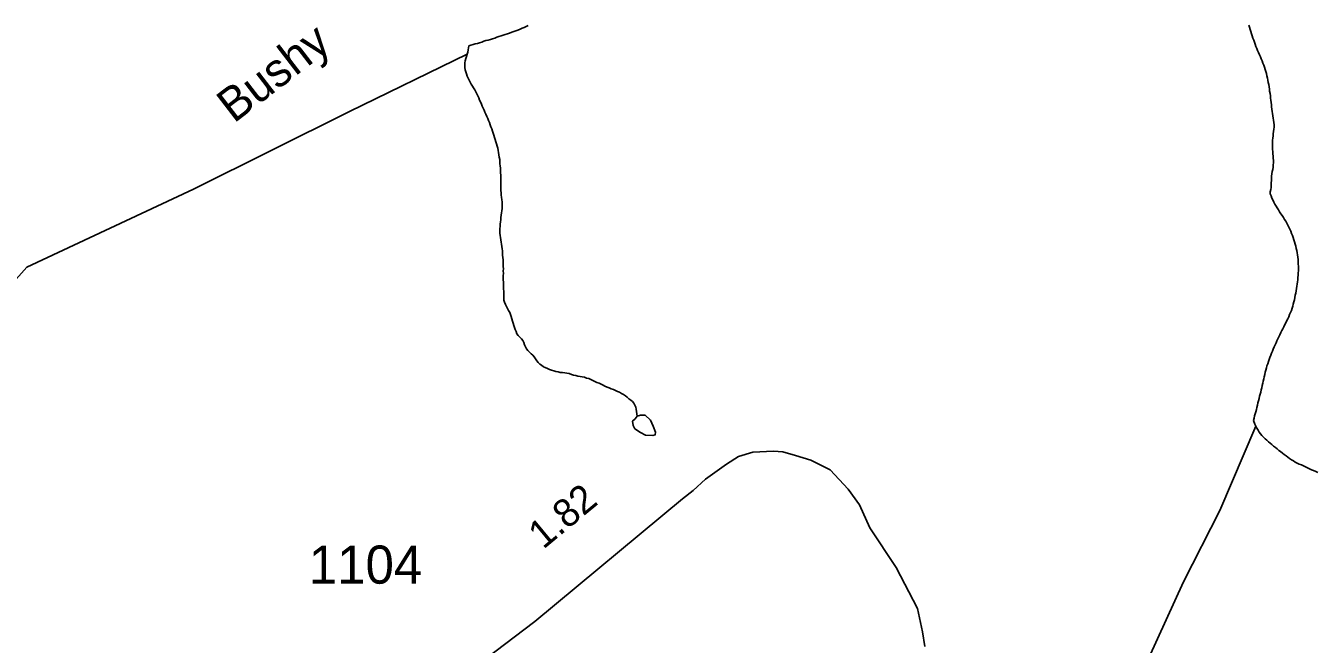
# Model space of a CAD drawing. Extents: x 1950930 to 2061844, y 904556 to 1017002.
# Drawn here: x 1968619 to 1974370, y 911322 to 914077 of the extents above; entities that cross this region are included whole.
import ezdxf

# ---------------------------------------------------------------- set-up
doc = ezdxf.new("R2010")
doc.units = 0
for name, color, linetype in [('Exist Hydrographic Creek Single Shore', 7, 'Continuous'), ('Exist Hydrographic Creek Single Shore Label', 7, 'Continuous'), ('Exist Hydrographic Misc Water Feature', 7, 'Continuous'), ('Exist Road Primary US Structure Standard Bridge CELL', 7, 'Continuous'), ('Exist Road Secondary Type 51 Attributed', 7, 'Continuous'), ('Exist Road Secondary Type 51 Number Label', 7, 'Continuous')]:
    doc.layers.add(name, color=color, linetype=linetype)

msp = doc.modelspace()

# ---------------------------------------------------------------- linework, layer by layer
at = {"layer": 'Exist Hydrographic Creek Single Shore'}
for points in [[(1970593.6, 913987.5), (1970603.4, 913990), (1970613.3, 913993), (1970622.3, 913996.1), (1970631.9, 913998.2), (1970641.4, 914001.3), (1970651.2, 914004.3), (1970660.6, 914007.7), (1970670.1, 914010.6), (1970679.9, 914012.9), (1970689.8, 914015.9), (1970699.2, 914018.8), (1970709, 914021.8), (1970718.5, 914025.3), (1970727.9, 914028.3), (1970737.3, 914031.3), (1970746.8, 914034.3), (1970756.2, 914037.4), (1970765.6, 914040.8), (1970775.1, 914043.9), (1970784.7, 914047.7), (1970794.1, 914050.7), (1970803.1, 914054.5), (1970812.2, 914057.7), (1970821.8, 914061.5), (1970831, 914065.4), (1970840.1, 914069.7), (1970849.7, 914073.1), (1970858.5, 914077.4)], [(1974201.5, 913256), (1974196.1, 913265), (1974191.2, 913273.5), (1974186.3, 913282.7), (1974181.6, 913291.6), (1974177.1, 913300.7), (1974172.6, 913309.2), (1974169.1, 913319), (1974165.4, 913328.1), (1974164.8, 913337.1), (1974168.3, 913346.8), (1974169.1, 913356.8), (1974169.3, 913366.5), (1974169.9, 913377.3), (1974170.3, 913387.1), (1974170.7, 913397.1), (1974171.3, 913406.8), (1974172.2, 913416.8), (1974174.4, 913427), (1974176, 913436.9), (1974177.7, 913446.7), (1974178.9, 913456.8), (1974179.1, 913466.4), (1974179.1, 913476.2), (1974178.7, 913486.4), (1974178.3, 913496.3), (1974177.3, 913505.7), (1974176.5, 913516.4), (1974175.6, 913526.2), (1974174.8, 913536.6), (1974174.6, 913546.3), (1974174.6, 913556), (1974175.4, 913566.8), (1974176.3, 913576.4), (1974177.5, 913586.4), (1974178.7, 913596), (1974179.9, 913606), (1974181.6, 913615.8), (1974182, 913625.6), (1974182, 913636), (1974181.2, 913646.4), (1974179.7, 913655.9), (1974178.1, 913665.8), (1974176.3, 913675.9), (1974175.4, 913685.7), (1974173.6, 913695.4), (1974172.8, 913705.2), (1974171.3, 913715.2), (1974170.5, 913725.1), (1974169.1, 913735), (1974167.8, 913745), (1974166.8, 913754.8), (1974165.6, 913764.8), (1974164.4, 913775.1), (1974162.5, 913785.1), (1974161.3, 913795), (1974160.1, 913805), (1974158.2, 913814.6), (1974156.4, 913823.8), (1974154.5, 913833.8), (1974152.5, 913843.5), (1974150.6, 913853.5), (1974148.6, 913863.5), (1974145.5, 913873.4), (1974142.6, 913882.3), (1974139.8, 913892.4), (1974136.1, 913901.6), (1974132.6, 913910.6), (1974129.1, 913920.5), (1974125, 913929.6), (1974121.1, 913938.8), (1974117, 913947.9), (1974113.1, 913957), (1974109, 913966.1), (1974105.1, 913975.3), (1974101.6, 913984.7), (1974098.3, 913994.1), (1974094.8, 914003.2), (1974091.4, 914013.1), (1974088.3, 914022), (1974085.2, 914031.9), (1974081.7, 914041.3), (1974078.6, 914051.1), (1974075.6, 914060.9), (1974072.9, 914070.2), (1974070.2, 914079.9)], [(1970586.4, 913949.9), (1970588.9, 913959.7), (1970590.7, 913969.6), (1970593.6, 913987.5)], [(1968138.7, 912457.9), (1968623.6, 913001.1), (1969367.4, 913348.2), (1970061.6, 913695.3), (1970586.4, 913949.9)], [(1970747.6, 912994.1), (1970747.2, 913003.9), (1970747, 913013.7), (1970746.6, 913023.4), (1970746.6, 913033.6), (1970745.7, 913044.2), (1970744.5, 913054.2), (1970743.5, 913063.7), (1970743.1, 913073.9), (1970741.6, 913083.5), (1970740.8, 913093.3), (1970739.4, 913103.3), (1970738.1, 913113.2), (1970736.3, 913123.2), (1970734.2, 913132.9), (1970732.8, 913142.9), (1970732, 913152.7), (1970731.4, 913162.5), (1970732, 913173), (1970732.8, 913183), (1970733.6, 913193), (1970734.7, 913202.6), (1970735.9, 913212.6), (1970736.7, 913222.2), (1970738.6, 913232.9), (1970739.8, 913242.8), (1970741.4, 913252.8), (1970742.7, 913262.7), (1970742.7, 913272.5), (1970742, 913282.2), (1970741.6, 913292), (1970740.6, 913302), (1970740, 913312.6), (1970738.6, 913322.6), (1970738.1, 913332.3), (1970736.7, 913342.3), (1970736.3, 913352.1), (1970735.9, 913362), (1970735.7, 913371.7), (1970735.7, 913382.3), (1970735.7, 913392.4), (1970736.1, 913402), (1970736.1, 913411.8), (1970735.5, 913421.6), (1970734.9, 913432.3), (1970734.5, 913442.5), (1970733.8, 913452.3), (1970732.4, 913461.8), (1970731.6, 913471.8), (1970731.2, 913481.5), (1970729.3, 913491.5), (1970728.1, 913501.5), (1970726.3, 913511.5), (1970724.4, 913521.1), (1970722.4, 913531.1), (1970719.7, 913540.9), (1970717.2, 913551), (1970714.4, 913559.9), (1970711.3, 913569.8), (1970708.2, 913579.2), (1970705.5, 913588.9), (1970702.5, 913597.9), (1970699, 913607.8), (1970696.3, 913617.1), (1970692.4, 913627), (1970689.3, 913636), (1970685.2, 913645.1), (1970681.8, 913655.1), (1970678.3, 913664.1), (1970673.8, 913673.3), (1970669.9, 913682.5), (1970665.8, 913691.6), (1970661.9, 913700.7), (1970657.8, 913709.8), (1970653.9, 913719), (1970649.8, 913728.1), (1970645.9, 913737.2), (1970641.8, 913745.9), (1970637.7, 913755), (1970633.8, 913764.2), (1970628.9, 913773.5), (1970624.5, 913782.6), (1970620, 913791.8), (1970615.1, 913799.9), (1970610, 913808.4), (1970604.7, 913817.3), (1970599.3, 913825.9), (1970595, 913835), (1970590.3, 913843), (1970586.4, 913853), (1970582.9, 913862.4), (1970579.8, 913872.2), (1970577.6, 913881.1), (1970575.3, 913891.2), (1970575.3, 913900.9), (1970575.9, 913911.8), (1970577.8, 913921.2), (1970580.3, 913931), (1970583.5, 913940.2), (1970586.4, 913949.9)], [(1974090.3, 912318.9), (1974092.8, 912328.6), (1974095.3, 912338.4), (1974098.1, 912348.1), (1974100.6, 912357.1), (1974103.5, 912366.8), (1974105.5, 912376.7), (1974108, 912386.8), (1974110.4, 912396.6), (1974113.5, 912406.3), (1974116, 912416.1), (1974118, 912425.9), (1974120.7, 912434.8), (1974122.7, 912444.7), (1974125.2, 912454.4), (1974127.2, 912464.2), (1974129.7, 912474), (1974131.8, 912483.8), (1974134, 912493.7), (1974136.5, 912503.4), (1974138.5, 912513.2), (1974140.6, 912523.1), (1974143, 912532.8), (1974145.9, 912542.6), (1974148, 912552.4), (1974150.6, 912561.3), (1974153.7, 912571), (1974157, 912580.7), (1974160.3, 912589.9), (1974163.9, 912599.5), (1974167.6, 912608.7), (1974171.3, 912618.2), (1974174.8, 912627.5), (1974178.9, 912636.2), (1974182.6, 912646.1), (1974186.7, 912654.8), (1974191.2, 912664), (1974195.1, 912672.7), (1974199.4, 912682.5), (1974203.3, 912691.2), (1974207.8, 912700.4), (1974211.9, 912709.5), (1974217.3, 912718.4), (1974221.8, 912727), (1974226.1, 912736.1), (1974230.6, 912745.2), (1974235.1, 912753.9), (1974239.2, 912763), (1974243.5, 912771.6), (1974247.6, 912780.7), (1974251.7, 912789.9), (1974255.8, 912799.4), (1974259.5, 912808.5), (1974262.4, 912818.3), (1974265.2, 912828), (1974267.7, 912836.9), (1974270.6, 912846.7), (1974272.6, 912856.5), (1974274.7, 912866.3), (1974276.7, 912876.2), (1974278.8, 912885.9), (1974280.8, 912895.8), (1974282.3, 912906.5), (1974283.9, 912916.5), (1974284.9, 912926), (1974286.6, 912935.9), (1974287.4, 912945.5), (1974288.6, 912955.4), (1974289.4, 912965.5), (1974290.3, 912975.1), (1974290.7, 912986), (1974290.7, 912995.7), (1974290.7, 913005.5), (1974290.1, 913015.3), (1974289.9, 913026), (1974289.2, 913035.7), (1974288, 913045.7), (1974287, 913055.6), (1974285.7, 913065.6), (1974283.7, 913075.6), (1974281.4, 913085.2), (1974279.2, 913094.6), (1974276.5, 913104.2), (1974273, 913114.2), (1974270.4, 913123.5), (1974266.9, 913133.3), (1974263.6, 913142.3), (1974260.1, 913151.4), (1974256.2, 913161.3), (1974252.3, 913170.4), (1974247.8, 913179.7), (1974243.7, 913188), (1974238.8, 913196.8), (1974233.9, 913206.1), (1974229, 913214.1), (1974224, 913222.6), (1974218.1, 913231.2), (1974212.8, 913239.3), (1974206.8, 913247.5), (1974201.5, 913256)], [(1971343.3, 912337.7), (1971341.8, 912347.7), (1971341, 912357.6), (1971340.2, 912368.3), (1971337.9, 912377.9), (1971334.2, 912386.2), (1971328.5, 912394.8), (1971322.5, 912402.2), (1971315.2, 912409), (1971307.4, 912415.4), (1971299.2, 912422.4), (1971291.2, 912428), (1971283.2, 912434.1), (1971274.6, 912439.1), (1971265.3, 912444.6), (1971256.1, 912448), (1971246.9, 912451.4), (1971237.9, 912455.6), (1971228.4, 912459.9), (1971219.2, 912463.3), (1971210, 912466.8), (1971200.5, 912471.1), (1971191.9, 912475.2), (1971182.9, 912479.8), (1971173.9, 912484), (1971164.7, 912488.2), (1971155.6, 912492.5), (1971146.6, 912496.7), (1971137.4, 912500.1), (1971127.9, 912504.8), (1971118.7, 912507.5), (1971108.9, 912510.6), (1971099, 912512.4), (1971089.2, 912514.4), (1971079.8, 912516.2), (1971069.9, 912518.2), (1971060.1, 912520.8), (1971050.8, 912523.5), (1971041.2, 912527), (1971031.2, 912528.8), (1971021.3, 912530.4), (1971011.3, 912531.5), (1971001.2, 912532.6), (1970991.4, 912534.6), (1970982, 912536.4), (1970972.1, 912539.1), (1970962.5, 912541.7), (1970953.2, 912545.2), (1970944.2, 912549.4), (1970934.6, 912553.7), (1970926, 912557.8), (1970917.8, 912564), (1970909.8, 912569.6), (1970902.8, 912576.4), (1970896.9, 912584.6), (1970891.1, 912593.2), (1970884.8, 912601.4), (1970878.4, 912608.9), (1970871, 912615.8), (1970864.3, 912623.3), (1970856.9, 912630), (1970851.1, 912638.2), (1970846, 912646.7), (1970842.5, 912655.8), (1970838.6, 912665.7), (1970834.1, 912674.1), (1970827.8, 912682.4), (1970820.8, 912689.1), (1970813.6, 912696.7), (1970808.1, 912704.9), (1970804.2, 912714), (1970800.5, 912723), (1970797.4, 912732), (1970794.3, 912741.9), (1970791.5, 912752), (1970788.6, 912760.9), (1970785.9, 912770.7), (1970783, 912780.9), (1970778.9, 912790.1), (1970775.9, 912799.1), (1970771, 912808.3), (1970766.4, 912817.1), (1970761.3, 912826.5), (1970757.2, 912834.8), (1970753.3, 912844.7), (1970750.4, 912853.6), (1970749.6, 912863.5), (1970750, 912873.6), (1970750, 912884.1), (1970749.6, 912893.9), (1970749, 912903.8), (1970748.2, 912913.6), (1970748.2, 912923.4), (1970747.8, 912934), (1970747.4, 912944.2), (1970747.2, 912953.9), (1970747.2, 912963.7), (1970747.6, 912973.4), (1970747.2, 912984.4), (1970747.6, 912994.1)], [(1974377.2, 912086.5), (1974368, 912090.7), (1974358.5, 912095), (1974349.3, 912098.5), (1974340.3, 912102.7), (1974331.3, 912107.3), (1974322.2, 912111.5), (1974313.2, 912115.8), (1974304, 912120), (1974294.6, 912124.3), (1974285.5, 912128.5), (1974276.9, 912133.1), (1974268.3, 912138), (1974259.5, 912143), (1974251.5, 912149.1), (1974243.5, 912154.7), (1974235.7, 912160.9), (1974227.3, 912166.6), (1974219.7, 912172.6), (1974211.5, 912179.5), (1974203.5, 912185.2), (1974195.7, 912191.2), (1974188.3, 912197.7), (1974180.4, 912203.7), (1974172.6, 912210.6), (1974164.8, 912217.5), (1974157.6, 912223), (1974149.8, 912229.9), (1974142, 912236.7), (1974134.6, 912243.2), (1974127.9, 912250.7), (1974121.9, 912258.5), (1974116.4, 912266.6), (1974110.6, 912275.2), (1974106.1, 912284), (1974100.8, 912292.5), (1974096.5, 912301.7), (1974090.3, 912318.9)], [(1973491.4, 910849.6), (1973547.4, 911091.1), (1973778.6, 911599.7), (1973940.4, 911917.5), (1974100.8, 912292.5)]]:
    msp.add_lwpolyline(points, dxfattribs=at)
at = {"layer": 'Exist Hydrographic Misc Water Feature'}
msp.add_lwpolyline([(1971343.3, 912337.7), (1971359, 912341.4), (1971379.1, 912342), (1971403.1, 912320.1), (1971415.2, 912293.5), (1971425.7, 912266.4), (1971424, 912254.1), (1971413.4, 912252), (1971381.8, 912253.1), (1971359.5, 912265), (1971333.4, 912281.2), (1971325.4, 912295.4), (1971323.4, 912315.3), (1971335.3, 912325.6), (1971343.3, 912337.7)], dxfattribs=at)
at = {"layer": 'Exist Road Secondary Type 51 Attributed'}
msp.add_lwpolyline([(1970493.8, 911124.4), (1970888.1, 911423.1), (1971545.6, 911968.7), (1971593.4, 912005.9), (1971648.8, 912056.8), (1971742.6, 912123.3), (1971795.7, 912157.5), (1971860, 912176.7), (1971951.6, 912181.5), (1971992.6, 912179.3), (1972049, 912162.7), (1972117.6, 912141.7), (1972204.4, 912098.3), (1972284.2, 912012.8), (1972334.3, 911942.9), (1972380.8, 911839.7), (1972498.5, 911662.8), (1972593.7, 911480.8), (1972616.1, 911377.2), (1972625.9, 911311.3)], dxfattribs=at)

# ---------------------------------------------------------------- texts
at = {"layer": 'Exist Hydrographic Creek Single Shore Label'}
msp.add_text('Bushy', height=150, rotation=37.58289, dxfattribs=at).set_placement((1969546.5, 913639.6))
at = {"layer": 'Exist Road Primary US Structure Standard Bridge CELL'}
msp.add_text('1.82', height=125, rotation=39.68617, dxfattribs=at).set_placement((1970925.2, 911741.6))
at = {"layer": 'Exist Road Secondary Type 51 Number Label'}
msp.add_text('1104', height=170, dxfattribs=at).set_placement((1969880.6, 911591.2))

doc.saveas('drawing.dxf')
